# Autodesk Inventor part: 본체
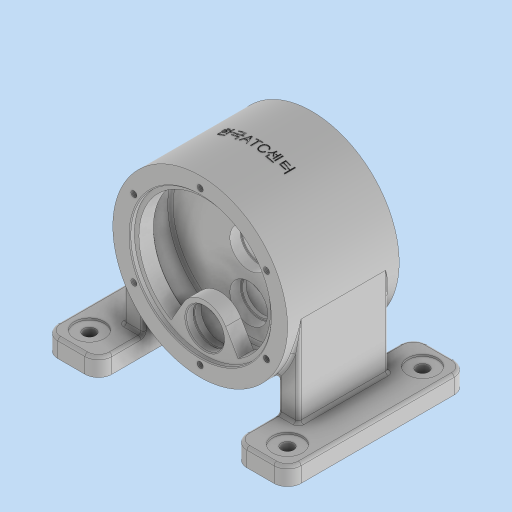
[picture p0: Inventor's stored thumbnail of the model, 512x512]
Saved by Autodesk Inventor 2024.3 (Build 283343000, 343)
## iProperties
Created: 2025-12
Part Number: 본체
Material: 일반
Document SubType Name: Modeling
Designer: PC2-02
Density: 1 g/cm^3
Appearance: 기본값
Author: PC2-02
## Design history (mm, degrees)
sketch "스케치1"
  geometry: L1 (-135, 100)-(135, 100); L2 (135, 100)-(135, -100); L3 (135, -100)-(-135, -100); L4 (-135, -100)-(-135, 100); 1 further point
  constraints: 8 end point, 2 parallel, 1 horizontal, 1 perpendicular
  dimensions: "d0" = 270 distance between parallel lines of L2 L4; "d1" = 135 distance from line of point (0, 0) L4; "d2" = 200 distance between parallel lines of L3 L1; "d3" = 100 distance from line of L3 point (0, 0)
extrude "돌출1" new body sketch "스케치1" distance "d4" = 20; taper "d5" = 0 deg
sketch "스케치2"
  geometry: L1 (135, 0)-(-135, 0) reference; C1 r 97 at (0, 120); 2 further points
  constraints: 1 centre point, 1 midpoint, 1 vertical alignment
  dimensions: "d6" = 194 diameter of C1; "d7" = 120 distance from line of L1 C1.centre
extrude "돌출2" join sketch "스케치2" stored distance "d8" = 124; taper "d9" = 0 deg
sketch "스케치3"
  geometry: L1 (0, 20)-(270, 20) reference; L2 (0, 0)-(270, 0) reference; L3 (60, 20)-(210, 20); L4 (210, 20)-(210, 0); L5 (210, 0)-(60, 0); L6 (60, 0)-(60, 20); L7 (0, 0)-(0, 20) reference; L8 (270, 0)-(270, 20) reference; 3 further points
  constraints: 8 end point, 2 parallel, 2 point on line, 1 horizontal, 1 perpendicular
  dimensions: "d10" = 60 distance between parallel lines of L7 L6; "d11" = 60 distance between parallel lines of L8 L4
extrude "돌출3" cut sketch "스케치3" extent not by distance; stored distance "d12" = 0; taper "d13" = 0 deg
sketch "스케치4"
  geometry: L1 (75, 50)-(97, 50); L2 (97, 50)-(97, -50); L3 (97, -50)-(75, -50); L4 (75, -100)-(75, 100) reference; L5 (75, -50)-(75, 50); L6 (-75, 100)-(-75, -100) reference; L7 (-75, 50)-(-97, 50); L8 (-97, 50)-(-97, -50); L9 (-97, -50)-(-75, -50); L10 (-75, -50)-(-75, 50); 2 further points
  constraints: 16 end point, 3 parallel, 3 point on line, 2 horizontal, 2 perpendicular, 1 collinear
  dimensions: "d14" = 100 distance between parallel lines of L3 L1; "d15" = 50 distance from line of L3 point (0, 0); "d16" = 22 distance between parallel lines of L2 L4; "d17" = 100 distance between parallel lines of L9 L7; "d18" = 50 distance from line of point (0, 0) L7; "d19" = 22 distance between parallel lines of L6 L8
extrude "돌출4" join sketch "스케치4" stored distance "d20" = 10; taper "d21" = 0 deg
sketch "스케치5"
  geometry: L1 (75, 20)-(75, 0) reference; L2 (75, 8)-(36.6, 30.17); L3 (75, 20)-(75, 58.486) reference; L4 (75, 0)-(135, 0) reference; L5 (-36.6, 30.17)-(-75, 8); L6 (-135, 0)-(-75, 0) reference; L7 (-75, 20)-(-75, 58.486) reference; L8 (-75, 0)-(-75, 20) reference; A1 r 97 centre (0, 120) between (36.6, 30.17) and (75, 58.486) reference; 2 further points
  constraints: 4 end point, 2 point on circle, 2 point on line
  dimensions: "d22" = 60 deg angle of L2 L3; "d23" = 8 distance from line of L4 L2.start; "d24" = 8 distance from line of L6 L5.end; "d25" = 60 deg angle of L7 L5
extrude "돌출5" join sketch "스케치5" stored distance "d26" = 12; taper "d27" = 0 deg
sketch "스케치6"
  geometry: C1 r 97 at (0, 0) reference; 2 further points
  constraints: 1 coincident
hole "구멍1" sketch "스케치6" at (0, 0) diameter "d28" = 146; stored, may be unused: countersink angle "d32" = 90 deg, drill point angle "d34" = 0 deg; dims "d29" = 6, "d30" = 156, "d31" = 5, "d33" = 17
sketch "스케치22"
  geometry: L1 (23.383, -39)-(49.148, -83.627); L2 (-23.383, -39)-(-49.148, -83.627); L3 (0, 0)-(0, -97); A1 r 27 centre (0, -52.5) between (23.383, -39) and (-23.383, -39); A2 r 97 centre (0, 0) between (49.148, -83.627) and (-49.148, -83.627) reference; 1 further point
  constraints: 6 end point, 5 point on circle, 2 tangent, 1 centre point, 1 vertical, 1 vertical alignment
  dimensions: "d152" = 52.5 distance of L3.start A1.centre; "d153" = 27 radius of A1; "d154" = 30 deg angle of L3 L2; "d155" = 60 deg angle of L1 L2
extrude "돌출8" join sketch "스케치22" distance "d156" = 22; taper "d157" = 0 deg
sketch "스케치23"
  geometry: C1 r 97 at (0, 0) reference; 2 further points
  constraints: 1 coincident
hole "구멍12" sketch "스케치23" at (0, 0) diameter "d158" = 156; stored, may be unused: countersink angle "d162" = 90 deg, drill point angle "d164" = 0 deg; dims "d159" = 6, "d160" = 4, "d161" = 2, "d163" = 5
sketch "스케치7"
  geometry: C1 r 97 at (0, 0) reference; 2 further points
  constraints: 1 coincident
hole "구멍2" sketch "스케치7" at (0, 0) diameter "d35" = 42; stored, may be unused: countersink angle "d39" = 90 deg, drill point angle "d41" = 0 deg; dims "d36" = 6, "d37" = 174, "d38" = 32, "d40" = 12
sketch "스케치8"
  geometry: C1 r 97 at (0, 0) reference; 2 further points
  constraints: 1 coincident
hole "구멍3" sketch "스케치8" at (0, 0) diameter "d42" = 146; stored, may be unused: countersink angle "d46" = 90 deg, drill point angle "d48" = 0 deg; dims "d43" = 6, "d44" = 156, "d45" = 5, "d47" = 17
sketch "스케치9"
  geometry: C1 r 97 at (0, 0) reference; 2 further points
  constraints: 1 coincident
hole "구멍4" sketch "스케치9" at (0, 0) diameter "d49" = 174; stored, may be unused: countersink angle "d53" = 90 deg, drill point angle "d55" = 0 deg; dims "d50" = 6, "d51" = 4, "d52" = 2, "d54" = 32
sketch "스케치11"
  geometry: A1 r 27 centre (0, -52.5) between (23.383, -39) and (-23.383, -39) reference; 2 further points
  constraints: 1 coincident
hole "구멍5" sketch "스케치11" at (0, -52.5) diameter "d63" = 42; stored, may be unused: countersink angle "d67" = 90 deg, drill point angle "d69" = 0 deg; dims "d64" = 6, "d65" = 4, "d66" = 2, "d68" = 8.05
sketch "스케치12"
  geometry: A1 r 27 centre (0, 0) between (23.383, 13.5) and (-23.383, 13.5) reference; 2 further points
  constraints: 1 coincident
hole "구멍6" sketch "스케치12" at (0, 0) diameter "d70" = 42; stored, may be unused: countersink angle "d74" = 90 deg, drill point angle "d76" = 0 deg; dims "d71" = 6, "d72" = 44.5, "d73" = 1.95, "d75" = 12
sketch "스케치17"
  geometry: A1 r 27 centre (0, -52.5) between (23.383, -39) and (-23.383, -39) reference; 2 further points
  constraints: 1 coincident
hole "구멍11" sketch "스케치17" at (0, -52.5) diameter "d123" = 38; stored, may be unused: countersink angle "d127" = 90 deg, drill point angle "d129" = 0 deg; dims "d124" = 6, "d125" = 42, "d126" = 12, "d128" = 12
sketch "스케치14" dims "d84" = 170
  geometry: C1 r 97 at (0, 0) reference; 3 further points
  constraints: 2 vertical alignment, 3 other
hole "구멍8" sketch "스케치14" at (0, 85) diameter "d85" = 6.647; stored, may be unused: countersink angle "d89" = 90 deg, drill point angle "d91" = 118 deg; dims "d86" = 16, "d87" = 4, "d88" = 2, "d90" = 18
sketch "스케치15"
  geometry: 2 further points
  dimensions: "d95" = 110 horizontal distance of point (0, 0) point (-110, -75); "d96" = 75 vertical distance of point (0, 0) point (-110, -75)
hole "구멍9" sketch "스케치15" at (-110, -75) diameter "d97" = 13.5; stored, may be unused: countersink angle "d101" = 90 deg, drill point angle "d103" = 0 deg; dims "d98" = 6, "d99" = 33, "d100" = 2, "d102" = 17
fillet "모깎기1" dims "d110" = 15
fillet "모깎기3" dims "d112" = 3
fillet "모깎기4" dims "d113" = 3
fillet "모깎기5" dims "d114" = 3
fillet "모깎기6" dims "d115" = 3
sketch "스케치16"
  geometry: C1 r 21 at (0, 0) reference; 2 further points
  constraints: 1 coincident
hole "구멍10" sketch "스케치16" at (0, 0) diameter "d116" = 38; stored, may be unused: countersink angle "d120" = 90 deg, drill point angle "d122" = 0 deg; dims "d117" = 6, "d118" = 4, "d119" = 2, "d121" = 12
fillet "모깎기7" dims "d130" = 0.6
chamfer "모따기1" distance "d131" = 1; stored, may be unused: second distance "d132" = 2, angle "d133" = 45 deg
node "작업 평면1"
sketch "스케치18"
  geometry: L1 (-45, 6.5)-(45, 6.5); L2 (45, 6.5)-(45, -6.5); L3 (45, -6.5)-(-45, -6.5); L4 (-45, -6.5)-(-45, 6.5); L5 (-45, 0)-(45, 0); L6 (0, -6.5)-(0, 6.5); 3 further points
  constraints: 6 midpoint, 4 end point, 2 coincident, 1 vertical, 2 other
  dimensions: "d135" = 13 distance between parallel lines of L3 L1; "d136" = 90 distance between parallel lines of L4 L2
feature "엠보싱1" sketch "스케치18" dims "d137" = 0.5, "d138" = 0
fillet "모깎기8" dims "d144" = 3
fillet "모깎기9" dims "d145" = 3
fillet "모깎기10" dims "d146" = 3
node "솔리드1"
pattern_circular "원형 패턴1" dims angle "d93" = 360 deg
mirror "미러1"
pattern_linear "직사각형 패턴1" dims "d106" = 220, "d109" = 150
node "투영된 루프2"
feature "A9D066F2-1C7D-4E18-AEED-F7BC21143FA4" dims "d28" = 146, "d29" = 6, "d30" = 156, "d31" = 5, "d32" = 90 deg, "d33" = 17, "d34" = 0
other parameters: "d134" = 217
